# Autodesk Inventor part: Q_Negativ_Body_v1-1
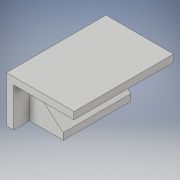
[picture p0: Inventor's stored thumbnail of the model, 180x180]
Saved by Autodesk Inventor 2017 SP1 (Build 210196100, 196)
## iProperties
Part Number: Q_Negativ_Body_v1-1
Material: Generisch
Document SubType Name: Modeling
Designer: haesner
Density: 1 g/cm^3
Appearance: Vorgabe
Part Number: Q_Negativ_Body_v1-1_3D-Druck
Author: haesner
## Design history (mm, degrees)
sketch "Skizze3"
  geometry: L1 (9.5, 9.5)-(0, 9.5); L2 (0, 9.5)-(0, -9.5); L3 (0, -9.5)-(9.5, -9.5); L4 (9.5, -9.5)-(9.5, 9.5); L5 (0, 13.3)-(0, -13.3) reference; L6 (-1.9, 0)-(11.4, 0) reference; 1 further point
  constraints: 8 end point, 2 parallel, 1 collinear, 1 horizontal, 1 perpendicular, 1 other
  dimensions: "d7" = 19 distance of L1.end L2.end; "d8" = 9.5 distance of L1.start L1.end (= 0.5 x d7)
extrude "Extrusion3" new body sketch "Skizze3" distance "d9" = 9; taper "d10" = 0 deg
sketch "Skizze4"
  geometry: L1 (1, -6.405)-(1, 6.435); L2 (0, 9.5)-(0, -9.5) reference; 1 further point
  constraints: 2 end point
  dimensions: "d12" = 1 distance between parallel lines of L2 L1
workplane "Arbeitsebene1"
  workaxis "Arbeitsachse1"
feature "Trennen1"
sketch "Skizze5"
  geometry: L1 (1, -9.5)-(1, 9.5) reference; L2 (1, 9.5)-(0, 9.5) reference; L3 (0, 9.5)-(0, -9.5) reference; L4 (0, -9.5)-(1, -9.5) reference; 1 further point
extrude "Extrusion4" join sketch "Skizze5" distance "d14" = 1; taper "d15" = 0 deg
sketch "Skizze6"
  geometry: L1 (9.5, 9.5)-(9.5, -9.5) reference; L2 (9.5, -9.5)-(1, -9.5) reference; L3 (1, 9.5)-(9.5, 9.5) reference; L4 (1, 9.5)-(0, 9.5) reference; L5 (0, -9.5)-(1, -9.5) reference; L6 (0, 9.5)-(0, -9.5) reference; 1 further point
extrude "Extrusion5" join sketch "Skizze6" distance "d16" = 1; taper "d17" = 0 deg
sketch "Skizze7"
  geometry: L1 (0, -14)-(0, 14); L2 (0, -23.8)-(0, 23.8) reference; L3 (0, 14)-(17, 14); L4 (17, 14)-(17, -14); L5 (17, -14)-(0, -14); L6 (-5.8, 0)-(20.8, 0) reference; 1 further point
  constraints: 8 end point, 1 collinear, 1 horizontal, 1 parallel, 1 perpendicular, 1 other
  dimensions: "d26" = 17 distance of L1.end L3.end; "d27" = 28 distance of L3.end L4.end
extrude "Extrusion6" join sketch "Skizze7" distance "d19" = 2; taper "d20" = 0 deg
sketch "Skizze8"
  geometry: L1 (0, -4.5)-(13, -4.5); L2 (13, -4.5)-(13, 23.5); L3 (13, 23.5)-(0, 23.5); L4 (0, 23.5)-(0, -4.5); L5 (-2.6, 9.5)-(15.6, 9.5) reference; L6 (0, -10.1)-(0, 29.1) reference; L7 (13, 23.5)-(13, -4.5) reference; L8 (0, 19)-(0, 0) reference; 1 further point
  constraints: 8 end point, 2 collinear, 2 parallel, 1 horizontal, 1 perpendicular, 1 other
  dimensions: "d21" = 28 distance of L3.end L1.start
extrude "Extrusion7" join sketch "Skizze8" distance "d22" = 2; taper "d23" = 0 deg
node "Volumenkörper1"
node "Volumenkörper2"
node "Projizierte Kontur1"
other parameters: "d13" = 40 deg
